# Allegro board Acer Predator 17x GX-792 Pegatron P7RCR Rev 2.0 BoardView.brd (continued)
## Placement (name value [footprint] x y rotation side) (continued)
C18107  10UF/6.3V  [VX_C0402_H28_SMALL]  114.38 63.02 0 bottom
C18108  1UF/6.3V  [VX_C0402_SMALL]  114.41 54.16 0 bottom
C18109  10UF/6.3V  [VX_C0402_H28_SMALL]  114.41 53.32 0 bottom
C18110  1UF/6.3V  [VX_C0402_SMALL]  114.41 52.48 0 bottom
C18111  10UF/6.3V  [VX_C0402_H28_SMALL]  114.38 63.89 0 bottom
C18112  1UF/6.3V  [VX_C0402_SMALL]  114.38 65.56 0 bottom
C75100  1UF/6.3V  [VX_C0402_SMALL]  155.29 91.11 180 top
C75101  1UF/6.3V  [VX_C0402_SMALL]  158.44 91.11 0 top
C75102  1UF/6.3V  [VX_C0402_SMALL]  160.02 91.1 0 top
C75103  1UF/6.3V  [VX_C0402_SMALL]  156.86 91.11 0 top
C75104  10uF/6.3V  [VX_C0603_H39_SMALL]  169.19 93.89 270 top
C75105  1UF/6.3V  [VX_C0402_SMALL]  155.29 89.72 180 top
C75106  1UF/6.3V  [VX_C0402_SMALL]  158.44 89.72 0 top
C75107  1UF/6.3V  [VX_C0402_SMALL]  160.01 89.72 0 top
C75108  1UF/6.3V  [VX_C0402_SMALL]  171.4 90.05 270 top
C75109  1UF/6.3V  [VX_C0402_SMALL]  163.21 98.1 180 top
C75110  1UF/6.3V  [VX_C0402_SMALL]  164.81 98.1 180 top
C75111  1UF/6.3V  [VX_C0402_SMALL]  163.21 96.7 180 top
C75112  1UF/6.3V  [VX_C0402_SMALL]  164.81 96.7 180 top
C75113  1UF/6.3V  [VX_C0402_SMALL]  166.38 96.7 0 top
C75114  1UF/6.3V  [VX_C0402_SMALL]  167.96 96.7 0 top
C75115  1UF/6.3V  [VX_C0402_SMALL]  167.96 100.89 0 top
C75116  10uF/6.3V  [VX_C0603_H39_SMALL]  161.57 93.93 270 top
C75117  10uF/6.3V  [VX_C0603_H39_SMALL]  164.48 90.41 90 top
C75118  10uF/6.3V  [VX_C0603_H39_SMALL]  166 90.36 90 top
C75119  10uF/6.3V  [VX_C0603_H39_SMALL]  157.23 97.37 270 top
C75120  1UF/6.3V  [VX_C0402_SMALL]  160.02 88.3 0 top
C75121  1UF/6.3V  [VX_C0402_SMALL]  164.74 88.27 180 top
C75122  330UF/2V  [VX_C7343D_H83]  157.82 97.79 180 top
C75123  330UF/2V  [VX_C7343D_H83]  165.41 89.9 0 top
C75124  10uF/6.3V  [VX_C0603_H39_SMALL]  159.92 93.95 90 top
C75125  10uF/6.3V  [VX_C0603_H39_SMALL]  154.01 93.88 90 top
C75126  330UF/2V  [VX_C7343D_H83]  202.8 145.24 180 top
C75127  47uF/4V  [VX_C0805_H57_SMALL]  201.83 141.61 0 top
C75128  1UF/6.3V  [VX_C0402_SMALL]  169.53 100.89 0 top
C75129  1UF/6.3V  [VX_C0402_SMALL]  158.81 102.95 180 top
C75130  1UF/6.3V  [VX_C0402_SMALL]  161.65 100.99 0 top
C75131  1UF/6.3V  [VX_C0402_SMALL]  153.71 86.9 180 top
C75132  1UF/6.3V  [VX_C0402_SMALL]  159.98 84.87 0 top
C75133  1UF/6.3V  [VX_C0402_SMALL]  163.28 86.8 180 top
C75134  1UF/6.3V  [VX_C0402_SMALL]  166.38 100.89 180 top
C75135  1UF/6.3V  [VX_C0402_SMALL]  157.22 102.95 0 top
C75136  1UF/6.3V  [VX_C0402_SMALL]  163.23 100.89 180 top
C75137  1UF/6.3V  [VX_C0402_SMALL]  169.91 102.92 0 top
C75138  1UF/6.3V  [VX_C0402_SMALL]  164.08 102.95 0 top
C75139  1UF/6.3V  [VX_C0402_SMALL]  160.04 86.9 0 top
C75140  1UF/6.3V  [VX_C0402_SMALL]  156.88 86.9 0 top
C75141  1UF/6.3V  [VX_C0402_SMALL]  166.44 86.8 180 top
C75142  1UF/6.3V  [VX_C0402_SMALL]  169.6 86.8 0 top
C75143  1UF/6.3V  [VX_C0402_SMALL]  169.76 84.85 0 top
C75144  0.1UF/6.3V  [VX_C0402_SMALL]  153.6 84.44 90 top
C75145  1UF/6.3V  [VX_C0402_SMALL]  152.25 72.75 0 top
C75146  4.7uF/16V  [VX_C0603_SMALL]  152.5 82.97 180 top
C75147  0.1UF/6.3V  [VX_C0402_SMALL]  154.83 84.04 180 top
C75148  0.1UF/6.3V  [VX_C0402_SMALL]  156.07 84.38 90 top
C75149  4.7uF/16V  [VX_C0603_SMALL]  149.42 71.74 180 top
C75150  1UF/6.3V  [VX_C0402_SMALL]  152.25 71.86 0 top
C75151  0.1UF/6.3V  [VX_C0402_SMALL]  157.46 82.28 270 top
C75152  1UF/6.3V  [VX_C0402_SMALL]  152.25 70.97 0 top
C75153  4.7uF/16V  [VX_C0603_SMALL]  149.43 70.5 180 top
C75154  0.1UF/6.3V  [VX_C0402_SMALL]  156.91 84.4 90 top
C75155  0.1UF/6.3V  [VX_C0402_SMALL]  155.3 82.02 270 top
C75156  4.7uF/16V  [VX_C0603_SMALL]  127.45 83.61 90 top
C75157  1UF/6.3V  [VX_C0402_SMALL]  123.95 83.4 180 top
C75158  0.1UF/6.3V  [VX_C0402_SMALL]  152.15 85.09 0 top
C75159  0.1UF/6.3V  [VX_C0402_SMALL]  152.15 84.27 0 top
C75160  330UF/2V  [VX_C7343D_H83]  140.76 148.9 0 top
C75161  330UF/2V  [VX_C7343D_H83]  141.76 148.42 0 bottom
C80002  22UF/6.3V  [VX_C0603_H39_SMALL]  105.55 118.4 180 top
C80004  22UF/6.3V  [VX_C0603_H39_SMALL]  88.92 129.83 180 top
C80005  10UF/25V  [VX_C0805_H57_SMALL]  59.29 172.96 180 top
C80006  10UF/25V  [VX_C0805_H57_SMALL]  59.29 171.18 180 top
C80008  22UF/6.3V  [VX_C0603_H39_SMALL]  93.49 116.24 180 top
C80009  22UF/6.3V  [VX_C0603_H39_SMALL]  70.21 138.03 270 bottom
C80010  22UF/6.3V  [VX_C0603_H39_SMALL]  68.94 138.03 270 bottom
C80012  22UF/6.3V  [VX_C0603_H39_SMALL]  82.28 137.27 270 bottom
C80013  22UF/6.3V  [VX_C0603_H39_SMALL]  77.07 137.27 270 bottom
C80017  22UF/6.3V  [VX_C0603_H39_SMALL]  83.2 116.1 0 top
C80019  1UF/16V  [VX_C0402_SMALL]  57.38 165.46 180 top
C80020  22UF/6.3V  [VX_C0603_H39_SMALL]  102 129.83 0 top
C80022  22UF/6.3V  [VX_C0603_H39_SMALL]  85.49 129.83 0 top
C80023  22UF/6.3V  [VX_C0603_H39_SMALL]  63.81 147.68 180 top
C80024  22UF/6.3V  [VX_C0603_H39_SMALL]  75.8 137.27 270 bottom
C80025  1UF/25V  [VX_C0402_H24_SMALL]  67.67 169.91 90 top
C80026  22UF/6.3V  [VX_C0603_H39_SMALL]  102.76 118.4 0 top
C80027  1000PF/50V  [VX_C0402_SMALL]  53.57 171.81 180 top
C80029  22UF/6.3V  [VX_C0603_H39_SMALL]  100.69 146.16 0 top
C80031  22UF/6.3V  [VX_C0603_H39_SMALL]  110.98 129.67 90 top
C80032  22UF/6.3V  [VX_C0603_H39_SMALL]  63.81 148.95 180 top
C80036  22UF/6.3V  [VX_C0603_H39_SMALL]  98.34 129.83 180 top
C80038  22UF/6.3V  [VX_C0603_H39_SMALL]  102.76 117.13 0 top
C80039  22UF/6.3V  [VX_C0603_H39_SMALL]  63.81 146.41 180 top
C80040  22UF/6.3V  [VX_C0603_H39_SMALL]  93.11 129.93 180 top
C80041  1500PF/50V  [VX_C0603_SMALL]  90 159.11 0 top
C80042  0.22UF/16V  [VX_C0402_SMALL]  64.12 174.23 270 top
C80044  22UF/6.3V  [VX_C0603_H39_SMALL]  107.97 124.36 0 top
C80046  1500PF/50V  [VX_C0603_SMALL]  48.88 172.7 270 top
C80049  22UF/6.3V  [VX_C0603_H39_SMALL]  118.8 126.5 180 top
C80050  22UF/6.3V  [VX_C0603_H39_SMALL]  84.44 146.54 0 top
C80052  0.22UF/16V  [VX_C0402_SMALL]  57.26 168.05 270 top
C80055  22UF/6.3V  [VX_C0603_H39_SMALL]  104.54 129.83 0 top
C80056  1500PF/50V  [VX_C0603_SMALL]  59.54 164.95 0 top
C80057  22UF/6.3V  [VX_C0603_H39_SMALL]  81.81 129.83 180 top
C80059  22UF/6.3V  [VX_C0603_H39_SMALL]  100.69 144.89 0 top
C80062  22UF/6.3V  [VX_C0603_H39_SMALL]  84.82 137.27 270 bottom
C80064  1UF/16V  [VX_C0402_SMALL]  65 174.73 270 top
C80066  1UF/25V  [VX_C0402_H24_SMALL]  100.76 160 0 top
C80068  22UF/6.3V  [VX_C0603_H39_SMALL]  63.81 150.22 180 top
C80069  22UF/6.3V  [VX_C0603_H39_SMALL]  86.53 116.16 180 top
C80070  10UF/25V  [VX_C0805_H57_SMALL]  53.57 174.99 180 top
C80073  22UF/6.3V  [VX_C0603_H39_SMALL]  101.78 137.47 270 top
C80074  1000PF/50V  [VX_C0402_SMALL]  60.31 169.4 270 top
C80075  22UF/6.3V  [VX_C0603_H39_SMALL]  97.88 117.08 0 top
C80076  10UF/25V  [VX_C0805_H57_SMALL]  53.57 173.21 180 top
C80077  22UF/6.3V  [VX_C0603_H39_SMALL]  86.09 137.27 270 bottom
C80078  22UF/6.3V  [VX_C0603_H39_SMALL]  103.36 137.47 270 top
C80079  10UF/25V  [VX_C0805_H57_SMALL]  53.57 176.77 180 top
C80082  1UF/25V  [VX_C0402_H24_SMALL]  53.7 164.45 0 top
C80083  22UF/6.3V  [VX_C0603_H39_SMALL]  100.5 118.4 180 top
C80087  22UF/6.3V  [VX_C0603_H39_SMALL]  84.44 145.27 0 top
C80091  10UF/25V  [VX_C0805_H57_SMALL]  59.29 174.73 180 top
C80092  22UF/6.3V  [VX_C0603_H39_SMALL]  90.66 144.63 180 top
C80095  22UF/6.3V  [VX_C0603_H39_SMALL]  88.77 116.16 0 top
C80098  22UF/6.3V  [VX_C0603_H39_SMALL]  83.55 137.27 270 bottom
C80102  22UF/6.3V  [VX_C0603_H39_SMALL]  71.48 138.03 270 bottom
C80103  0.068UF/16V  [VX_C0402_SMALL]  49 190.18 90 top
C80104  0.1UF/25V  [VX_C0402_SMALL]  48.11 188.83 0 bottom
C80105  6800PF/25V  [VX_C0402_SMALL]  49.38 188.37 270 bottom
C80106  2200PF/50V  [VX_C0402_SMALL]  50.15 185.27 180 bottom
C80107  0.22UF/25V  [VX_C0603_SMALL]  54.72 188.75 180 top
C80108  1UF/25V  [VX_C0402_H24_SMALL]  54.66 188.27 180 bottom
C80109  0.1UF/25V  [VX_C0402_SMALL]  50.15 179.61 0 bottom
C80110  0.1UF/25V  [VX_C0402_SMALL]  69.3 180.75 0 bottom
C80111  0.1UF/25V  [VX_C0402_SMALL]  49.89 190.18 90 top
C80112  22UF/6.3V  [VX_C0603_H39_SMALL]  71.1 129.9 90 top
C80113  22UF/6.3V  [VX_C0603_H39_SMALL]  73.26 137.27 270 bottom
C80114  22UF/6.3V  [VX_C0603_H39_SMALL]  74.53 137.27 270 bottom
C80115  22UF/6.3V  [VX_C0603_H39_SMALL]  53.6 150.3 0 top
C80116  22UF/6.3V  [VX_C0603_H39_SMALL]  78.34 137.27 270 bottom
C80117  22UF/6.3V  [VX_C0603_H39_SMALL]  67.67 138.03 270 bottom
C80118  22UF/6.3V  [VX_C0603_H39_SMALL]  66.4 138.03 270 bottom
C80119  22UF/6.3V  [VX_C0603_H39_SMALL]  81.01 137.27 270 bottom
C80121  22UF/6.3V  [VX_C0603_H39_SMALL]  79.61 137.27 270 bottom
C80122  10PF/50V  [VX_C0402_SMALL]  107.82 115.73 180 top
C80123  2.2NF/50V  [VX_C0402_SMALL]  107.79 116.64 180 top
C80124  10PF/50V  [VX_C0402_SMALL]  74.44 129.44 270 top
C80125  2.2NF/50V  [VX_C0402_SMALL]  75.33 129.44 270 top
C80126  10PF/50V  [VX_C0402_SMALL]  107.68 125.71 180 top
C80127  2.2NF/50V  [VX_C0402_SMALL]  107.68 132.32 180 top
C80128  22UF/6.3V  [VX_C0603_H39_SMALL]  100.69 143.62 0 top
C80129  22UF/6.3V  [VX_C0603_H39_SMALL]  103.66 153.73 270 top
C80130  22UF/6.3V  [VX_C0603_H39_SMALL]  118.8 127.77 180 top
C80131  22UF/6.3V  [VX_C0603_H39_SMALL]  102.39 153.73 270 top
C80132  22UF/6.3V  [VX_C0603_H39_SMALL]  118.8 129.17 180 top
C80133  0.1UF/25V  [VX_C0402_SMALL]  50.15 178.72 0 bottom
C80134  0.1UF/25V  [VX_C0402_SMALL]  70.16 126.25 0 bottom
CE1225  100UF/6.3V  [VX_C3528]  307.47 27.29 0 bottom
CE1801  330UF/2V  [VX_C7343D_H83]  56.62 104.76 90 top
CE1802  330UF/2V  [VX_C7343D_H83]  44.68 109.96 270 bottom
CE1803  330UF/2V  [VX_C7343D_H83]  54.84 109.96 270 bottom
CE1804  330UF/2V  [VX_C7343D_H83]  49.76 109.96 270 bottom
CE5502  100UF/6.3V  [VX_C3528]  308.24 59.16 90 top
CE5503  100UF/6.3V  [VX_C3528]  307.93 70.21 90 top
CE6703  100UF/6.3V  [VX_C3528]  32.11 95.61 180 bottom
CE8000  470UF/2V  [VX_C7343D_3P]  92.82 148.83 180 bottom
CE8001  470UF/2V  [VX_C7343D_3P]  82.53 148.83 0 bottom
CE8004  470UF/2V  [VX_C7343D_3P]  52.43 153.78 0 top
CE8007  470UF/2V  [VX_C7343D_3P]  62.97 153.78 180 top
CE8017  15UF/25V  [VX_C3528_SANYO_H79]  70.72 153.78 180 bottom
CE8018  15UF/25V  [VX_C3528_SANYO_H79]  70.72 157.21 180 bottom
CE8020  15UF/25V  [VX_C3528_SANYO_H79]  70.72 160.64 180 bottom
CE8021  15UF/25V  [VX_C3528_SANYO_H79]  85.08 178.95 90 bottom
CE8022  15UF/25V  [VX_C3528_SANYO_H79]  88.51 178.95 90 bottom
CE8023  15UF/25V  [VX_C3528_SANYO_H79]  86.62 179.18 90 top
CE8024  15UF/25V  [VX_C3528_SANYO_H79]  70.34 172.32 180 bottom
CE8025  15UF/25V  [VX_C3528_SANYO_H79]  70.34 175.75 180 bottom
CE8026  15UF/25V  [VX_C3528_SANYO_H79]  70.34 175.75 180 top
CE8100  220UF/6.3V  [VX_CESMD_260X260_H240_COLAY]  281.92 80.12 270 bottom
CE8101  220UF/6.3V  [VX_CESMD_260X260_H240_COLAY]  255.89 30.46 180 bottom
CE8301  470UF/2V  [VX_C7343D_3P]  26.27 87.36 0 top
CE8700  470UF/2V  [VX_C7343D_3P]  140.7 154.62 0 bottom
CE8701  470UF/2V  [VX_C7343D_3P]  158.22 154.79 180 bottom
CE8702  470UF/2V  [VX_C7343D_3P]  158.09 148.95 180 top
CE8703  470UF/2V  [VX_C7343D_3P]  158.1 154.79 180 top
CE8704  470UF/2V  [VX_C7343D_3P]  182.35 154.79 180 bottom
CE8705  470UF/2V  [VX_C7343D_3P]  187.26 156.06 180 top
CE8706  470UF/2V  [VX_C7343D_3P]  158.1 148.95 180 bottom
CE8707  470UF/2V  [VX_C7343D_3P]  167.75 154.79 0 bottom
CE8708  470UF/2V  [VX_C7343D_3P]  167.87 154.79 0 top
CE8709  470UF/2V  [VX_C7343D_3P]  167.86 148.95 0 top
CE8710  470UF/2V  [VX_C7343D_3P]  167.75 148.95 0 bottom
CE8711  470UF/2V  [VX_C7343D_3P]  140.7 154.72 0 top
CE8716  100UF/25V  [VX_CESMD_260X260_PANASONIC]  166.99 188.42 270 bottom
CE8717  100UF/25V  [VX_CESMD_260X260_PANASONIC]  144.76 188.32 270 bottom
CE8718  100UF/25V  [VX_CESMD_260X260_PANASONIC]  156.01 188.32 270 bottom
CE8719  100UF/25V  [VX_CESMD_260X260_PANASONIC]  178.29 188.42 270 bottom
CE8900  470UF/2V  [VX_C7343D_H83]  222.08 79.74 180 bottom
CE8901  470UF/2V  [VX_C7343D_H83]  213.79 93.07 270 bottom
CE8902  470UF/2V  [VX_C7343D_H83]  222.36 79.74 180 top
CE8903  470UF/2V  [VX_C7343D_H83]  213.98 92.82 270 top
CE9701  470UF/2V  [VX_C7343D_3P]  189.85 149.05 0 top
CE9702  470UF/2V  [VX_C7343D_3P]  202.57 149.89 180 bottom
CE9703  470UF/2V  [VX_C7343D_3P]  189.85 149.08 0 bottom
CE9704  470UF/2V  [VX_C7343D_3P]  202.62 150.63 180 top
CN1  33PF/50V  [VX_C_ARRAY_8P_79X49_H39]  117.14 17.35 0 top
CN2  33PF/50V  [VX_C_ARRAY_8P_79X49_H39]  119.93 17.35 0 top
CN3  33PF/50V  [VX_C_ARRAY_8P_79X49_H39]  123.11 17.35 0 top
CN4  33PF/50V  [VX_C_ARRAY_8P_79X49_H39]  126.23 17.35 0 top
CN5  33PF/50V  [VX_C_ARRAY_8P_79X49_H39]  131.95 17.35 0 top
CN6  33PF/50V  [VX_C_ARRAY_8P_79X49_H39]  135.12 17.35 0 top
CN7  33PF/50V  [VX_C_ARRAY_8P_79X49_H39]  129.03 17.35 0 top
CON1  FPC_CON_8P  [VX_FPC_8P_20_2H_RA_ACE_B]  236.7 188.1 0 top
CON1201  USB_CON_24P  [VX_USB_24P_10HD_RA_ACON]  318.85 33.05 90 top
CON1600  DDR4_SO_260P  [VX_DDR4_260P_20_4HD_FOX]  76 60.7 0 top
CON1601  DDR4_SO_260P  [VX_DDR4_260P_20_4HOD_REV_FO]  74 60.7 180 bottom
CON1700  DDR4_SO_260P  [VX_DDR4_260P_20_4H_RE_H177]  76 48.7 180 top
CON1701  DDR4_SO_260P  [VX_DDR4_260P_20_4H_REV_ARGO]  74 48.7 180 bottom
CON2800  BATT_HOLDER_2P  [VX_BATHOLDER_2P_2HOLD]  298 61.9 270 bottom
CON3100  FPC_CON_26P  [VX_FPC_26P_39_2H_RA_B]  118 7.7 180 bottom
CON3104  FPC_CON_14P  [VX_FPC_14P_20_2H_ACE_B]  209 18.7 180 bottom
CON3110  FPC_CON_14P  [VX_FPC_14P_20_2HD_RA_ENTERY]  189.75 16.8 180 bottom
CON3400  LAN_JACK_8P  [VX_LAN_JACK_8P_2HD_SAN_LF2]  317.7 145.9 270 bottom
CON3600  WTOB_CON_4P  [VX_WTOB_4P_39_2H_ACES]  7 22.9 90 bottom
CON3700  WtoB_CON_4P  [VX_WTOB_4P_49_2HOLD_RA]  232 18.7 180 bottom
CON4400  FPC_CON_12P  [VX_FPC_12P_20_2HD_B]  144 5.7 180 bottom
CON4402  FPC_CON_12P  [VX_FPC_12P_20_2HD_B]  175.75 17.4 180 bottom
CON4500  WTOB_CON_40P  [VX_WTOB_40P_20_6HD_STAR]  112.5 186.2 0 top
CON4601  DISPLAY_CON_20P  [VX_DISPLAY_20P_39_4H_ACON]  320.02 123.95 90 top
CON4800  HDMI_CON_19P  [VX_HDMI_19P_4HLD_ACON]  321 100.85 90 top
CON5000  WTOB_CON_4P  [VX_WTOB_4P_49_2HD_ACE]  52 118.7 180 bottom
CON5001  WTOB_CON_4P  [VX_WTOB_4P_49_2HD_ACE]  261.8 88.15 0 bottom
CON5002  WTOB_CON_3P  [VX_WTOB_3P_49_2H_RA_ACE]  82.67 6.45 270 bottom
CON5100  WTOB_CON_20P  [VX_WTOB_20P_20_6HOLD_ENTERY]  20 11.9 180 bottom
CON5102  NGFF_67P  [VX_NGFF_67P_20_4HOLD_H165]  36.3 29.7 270 bottom
CON5103  MINI_PCI_67P  [VX_MINI_PCI_67P_20_4HLD_LOT]  25 29.7 270 bottom
CON5104  MINI_PCI_67P  [VX_MINI_PCI_67P_20_4HLD_LOT]  43.5 9.4 180 bottom
CON5300  MINI_PCI_67P  [VX_MINI_PCI_67P_20_4H_H128]  297 96.9 0 bottom
CON5500  USB_CON_9P  [VX_USB_9P_4HOLD_RA_SINGA]  312.9 52.2 90 top
CON5501  USB_CON_9P  [VX_USB_9P_4HOLD_RA_SINGA]  312.9 79.6 90 top
CON5602  FPC_CON_28P  [VX_FPC_CON_28P_20_2H_AC_B]  88.5 187.1 0 bottom
CON6000  WTOB_CON_10P  [VX_WTOB_10P_79_2HD_RA_CUIL]  295 18.42 180 bottom
CON6001  WTOB_CON_10P  [VX_WTOB_10P_59_4HOLD_RA_TYU]  11.5 69.4 90 bottom
CON6002  TACT_SWITCH_4P  [VX_SW_4P_146_S205_2HOLD_H63]  297 83.7 0 bottom
CON6003  SWITCH_4P  [VX_SW_4P_185X185]  26.99 71.9 90 bottom
CON6004  WTOB_CON_2P  [VX_WTOB_2P_49_2HOLD_ACE]  12.5 82.3 0 bottom
CON6700  FPC_CON_45P  [VX_FPC_45P_20_2H_RA_ENTE_B]  11 45.7 90 bottom
CON6701  WTOB_CON_5P  [VX_WTOB_5P_39_2HOLD_ENTE]  21.49 82.99 180 bottom
D1201  ESD8011MUT5G  [VX_ESD_2P_24X13_PAD8X10]  314.05 31.67 90 top
D1202  ESD8011MUT5G  [VX_ESD_2P_24X13_PAD8X10]  314.05 30.44 270 top
D1203  ESD8011MUT5G  [VX_ESD_2P_24X13_PAD8X10]  316.19 30.33 270 bottom
D1204  ESD8011MUT5G  [VX_ESD_2P_24X13_PAD8X10]  316.19 31.6 90 bottom
D1205  ESD8011MUT5G  [VX_ESD_2P_24X13_PAD8X10]  316.19 34.4 270 bottom
D1206  ESD8011MUT5G  [VX_ESD_2P_24X13_PAD8X10]  316.19 35.67 90 bottom
D1207  ESD8011MUT5G  [VX_ESD_2P_24X13_PAD8X10]  314.05 35.66 90 top
D1208  ESD8011MUT5G  [VX_ESD_2P_24X13_PAD8X10]  314.05 34.42 270 top
D1209  AZ5725-01F  [VX_ESD_2P_33_39X24_COLAY]  309.73 28.05 90 top
D1301  RB751V-40  [VX_SOD323_H35]  280.45 88.88 180 top
D2301  CH751H-40AGP  [VX_SOD323_H39]  242.22 79.53 180 top
D2401  CH751H-40AGP  [VX_SOD323_H39]  254.49 68.33 270 top
D2402  CH751H-40AGP  [VX_SOD323_H39]  252.58 70.59 270 top
D2801  0.8V/0.2mA  [VX_SOT323]  276.5 66.01 0 bottom
D3101  AZ5725-01F  [VX_ESD_2P_33_39X24_COLAY]  209.4 23.6 0 top
D3102  AZ5725-01F  [VX_ESD_2P_33_39X24_COLAY]  207.24 23.6 180 top
D3400  AZ5725-01F  [VX_ESD_2P_33_39X24_COLAY]  308.84 138.41 45 top
D3600  AZ5725-01F  [VX_ESD_2P_34_39X24_INPAQ]  4.81 45.96 270 top
D3601  CH751H-40AGP  [VX_SOD323_H39]  16.31 20.91 0 top
D4502  1V/0.1A  [VX_SOT323]  95.28 189.85 270 top
D4503  CH751H-40AGP  [VX_SOD323_H39]  91.29 189.47 90 top
D4800  BAW56W  [VX_SOT323]  308.34 88.43 180 top
D5000  0.8V/0.2mA  [VX_SOT323]  59.16 113.22 180 bottom
D5001  BAW56W  [VX_SOT323]  59.16 109.63 180 bottom
D5002  0.8V/0.2mA  [VX_SOT323]  266.15 87.08 180 top
D5003  BAW56W  [VX_SOT323]  261.88 86.28 90 top
D5004  1V/0.1A  [VX_SOT323]  136.89 39.5 180 top
D5301  CH751H-40AGP  [VX_SOD323_H39]  283.06 94.47 90 bottom
D5302  CH751H-40AGP  [VX_SOD323_H39]  281.16 94.47 90 bottom
D5303  1SS355AGP  [VX_SOD323_H37]  299.57 93.91 270 top
D5308  1SS355AGP  [VX_SOD323_H37]  299.57 98.53 270 top
D5501  AZ5725-01F  [VX_ESD_2P_33_39X24_COLAY]  307.45 47.57 270 bottom
D5502  AZ5725-01F  [VX_ESD_2P_33_39X24_COLAY]  308.76 47.57 270 bottom
D5503  AZ5725-01F  [VX_ESD_2P_33_39X24_COLAY]  307.88 78.44 270 bottom
D5504  AZ5725-01F  [VX_ESD_2P_33_39X24_COLAY]  307.88 80.6 90 bottom
D5505  AZ5725-01F  [VX_ESD_2P_33_39X24_COLAY]  308.34 63.86 90 top
D5506  AZ5725-01F  [VX_ESD_2P_33_39X24_COLAY]  309.2 74.91 90 top
D5601  1V/0.1A  [VX_SOT323]  94.85 185.3 0 top
D6002  AZ5725-01F  [VX_ESD_2P_33_39X24_COLAY]  293.1 28.94 270 bottom
D6003  AZ5725-01F  [VX_ESD_2P_33_39X24_COLAY]  291.6 30.36 90 bottom
D6005  1.25V/0.15A  [VX_SOT23_H49]  287.13 28.81 180 bottom
D6006  1.25V/0.15A  [VX_SOT23_H49]  287.13 32.11 180 bottom
D6701  AZ5725-01F  [VX_ESD_2P_33_39X24_COLAY]  16.75 32 270 bottom
D6702  AZ5725-01F  [VX_ESD_2P_33_39X24_COLAY]  16.75 34.2 90 bottom
D6703  AZ5725-01F  [VX_ESD_2P_33_39X24_COLAY]  12.63 38.97 0 top
D7401  0.8V/0.2mA  [VX_SOT323]  146.54 47.48 180 bottom
D7402  0.8V/0.2mA  [VX_SOT323]  151.11 59.09 90 bottom
D7403  0.8V/0.2mA  [VX_SOT323]  144.84 59.09 0 top
D7404  1.2V/0.1A  [VX_SOD323_H37]  141.71 58.91 180 bottom
D7405  0.8V/0.2mA  [VX_SOT323]  141.33 52.81 0 bottom
D7406  0.8V/0.2mA  [VX_SOT323]  141.59 62.47 180 top
D7407  1.2V/0.1A  [VX_SOD323_H37]  123.93 150.22 270 bottom
D8102  1V/0.2A  [VX_SOT23_H43]  259.7 73.31 90 top
D8103  1V/0.2A  [VX_SOT23_H43]  255.12 73.03 90 top
D8200  1.2V/0.1A  [VX_SOD323_H37]  191.37 18.65 0 top
D8300  1.2V/0.1A  [VX_SOD323_H37]  27.61 42.88 180 top
D8301  1.2V/0.1A  [VX_SOD323_H37]  32.44 42.88 180 top
D8601  1.2V/0.1A  [VX_SOD323_H37]  123.35 54.29 180 bottom
D8701  1.2V/0.1A  [VX_SOD323_H37]  124.44 160.13 0 bottom
D8800  0.8V/0.2mA  [VX_SOT323]  283.9 31.03 270 top
D8801  0.8V/0.2mA  [VX_SOT323]  3.94 61.63 180 top
D8804  1.2V/0.1A  [VX_SOD323_H37]  218.09 23.88 0 top
D8805  SBR2U30P1-7  [VX_POWERDI123]  266.33 34.88 0 top
D8900  1.2V/0.1A  [VX_SOD323_H37]  251.31 80.4 180 bottom
D9200  CH751H-40AGP  [VX_SOD323_H39]  178.57 42.25 180 top
D9201  1.2V/0.1A  [VX_SOD323_H37]  181.08 36.43 180 top
D9202  CH751H-40AGP  [VX_SOD323_H39]  185.91 36.23 270 top
D9400  1.2V/0.1A  [VX_SOD323_H37]  101.45 160.64 90 bottom
D9500  1.2V/0.1A  [VX_SOD323_H37]  101.2 14.84 180 bottom
D9600  1.2V/0.1A  [VX_SOD323_H37]  115.17 141.08 90 bottom
D9700  1.2V/0.1A  [VX_SOD323_H37]  208.01 186.54 90 top
H11  C138D118  [NB_H_RTD118_P2_S]  317.2 65.9 0 top
H21  RT335X350CBD118  [NB_H_RT335X350CBD118_P2_S]  319.8 21.6 0 top
H31  CT276B315D118  [VX_H_CT276CB315D118_P2]  43.5 166.8 180 top
H32  RT335X315B315D118  [NB_H_RT335X315B315D118_P2_S]  73.9 189.7 180 top
H33  ST335CB315D118  [VX_H_ST335CB315D118_P2]  316.5 163.9 180 bottom
H34  ST335CB315D118  [VX_H_ST335CB315D118_P2]  307.5 163.9 90 bottom
H35  RT335X315B315D118  [NB_H_RT335X315B315D118_P2_S]  188 189.7 0 top
H36  ST335CB315D118  [VX_H_ST335CB315D118_P2]  135.5 188.7 90 top
H51  CT276B315D118  [VX_H_CT276CB315D118_P2]  7 11.9 180 top
H52  CT276B315D118  [VX_H_CT276CB315D118_P2]  250 20.9 0 top
H53  CT276B315D118  [VX_H_CT276CB315D118_P2]  119.5 86.9 0 top
H54  CT276B315D118  [VX_H_CT276CB315D118_P2]  140 20.9 0 top
H55  CT276B315D118  [VX_H_CT276CB315D118_P2]  272 90.9 0 top
H56  CT276B315D118  [VX_H_CT276CB315D118_P2]  201 27.9 0 top
H60  CT256B256D130  [NB_NUT_CT256B256D130_LF2]  130.6 138.9 180 bottom
H61  CT256BD146  [NB_NUT_CT256B256D146_LF2]  106.62 145.85 180 bottom
H62  CT256BD146  [NB_NUT_CTB256D146_H91_LF2]  297 125.25 180 bottom
H63  CT256B256D130  [NB_NUT_CT256B256D130_LF2]  130.6 48.9 180 bottom
H64  CT256BD146  [NB_NUT_CT256B256D146_LF2]  68.14 113.56 180 bottom
H65  CT256BD146  [NB_NUT_C256D146_H134_LF2]  114.55 29.7 180 bottom
H66  CT256BD146  [NB_NUT_CT256B256D146_LF2]  115.34 96.38 180 bottom
H68  CT256B256D130  [NB_NUT_CT256B256D130_LF2]  192.6 138.9 270 bottom
H69  CT256B256D130  [NB_NUT_CT256B256D130_LF2]  192.6 48.9 180 bottom
H70  CT276B315D118  [VX_H_CT276CB315D118_P2]  50 97.9 0 top
H71  CT276B315D118  [VX_H_CT276CB315D118_P2]  27 60.9 0 top
H800  C102D102N  [HOLE_C102D102N]  249.05 189.45 0 bottom
H803  O134X102DO134X102N  [HOLE_O134X102DO134X102N]  223.95 189.45 0 bottom
H804  ST335CB315D118  [VX_H_ST335CB315D118_P2]  255.75 189.45 0 bottom
H805  ST335CB315D118  [VX_H_ST335CB315D118_P2]  218.25 189.45 0 bottom
H6901  O122X102DO122X102N  [HOLE_O122X102DO122X102N]  128.5 188.7 270 top
H6902  C102D102N  [HOLE_C102D102N]  75.8 10.5 270 top
H6903  O122X102DO122X102N  [HOLE_O122X102DO122X102N]  299.5 163.9 180 bottom
IC220  1UF/6.3V  [VX_C0402_SMALL]  1.96 55.53 0 top
IC221  1UF/6.3V  [VX_C0402_SMALL]  2.52 51.62 90 top
IU202  APL3518ABI-TRG  [VX_SOT23_S5_H57]  5.14 55.84 0 top
IU203  APL3518ABI-TRG  [VX_SOT23_S5_H57]  6.25 52.13 0 top
JP1001  3MM_OPEN_5MIL  [3MM_OPEN_5MIL_M1M2]  72.62 97.01 90 top
JP1201  3MM_OPEN_5MIL  [3MM_OPEN_5MIL_M1M2]  282.94 61.68 0 top
JP1601  3MM_OPEN_5MIL  [3MM_OPEN_5MIL_M1M2]  48.49 104.63 90 top
JP1701  3MM_OPEN_5MIL  [3MM_OPEN_5MIL_M1M2]  48.49 109.84 90 top
JP2601  2MM_OPEN_5MIL  [2MM_OPEN_5MIL_M1M2]  212.96 59.29 180 top
JP2602  1MM_OPEN_M1M2  [1MM_OPEN_5MIL_M1M2]  217.53 59.04 0 top
JP5601  SGL_JUMP  [NB_OPEN2_5MIL_PT]  84.94 189.59 90 top
JP8050  SHORT_PIN  [NB_PWR_FB_SHORT_PT]  79.13 155.56 180 bottom
JP8051  SHORT_PIN  [NB_PWR_FB_SHORT_PT]  82.63 155.56 0 bottom
JP8052  SHORT_PIN  [NB_PWR_FB_SHORT_PT]  79.13 171 180 bottom
JP8053  SHORT_PIN  [NB_PWR_FB_SHORT_PT]  82.63 170.97 0 bottom
JP8054  SHORT_PIN  [NB_PWR_FB_SHORT_PT]  79.13 163.3 180 bottom
JP8055  SHORT_PIN  [NB_PWR_FB_SHORT_PT]  82.63 163.3 0 bottom
JP8056  SHORT_PIN  [NB_PWR_FB_SHORT_PT]  92.94 150.48 180 top
JP8057  SHORT_PIN  [NB_PWR_FB_SHORT_PT]  54.31 160.38 0 top
JP8058  SHORT_PIN  [NB_PWR_FB_SHORT_PT]  50.81 160.38 180 top
JP8059  SHORT_PIN  [NB_PWR_FB_SHORT_PT]  64.47 160.38 0 top
JP8060  SHORT_PIN  [NB_PWR_FB_SHORT_PT]  60.97 160.38 180 top
JP8061  SHORT_PIN  [NB_PWR_FB_SHORT_PT]  96.27 150.48 0 top
JP8100  1MM_OPEN_M1M2  [1MM_OPEN_5MIL_M1M2]  266.68 60.31 270 top
JP8101  3MM_OPEN_5MIL  [3MM_OPEN_5MIL_M1M2]  283.44 74.47 0 top
JP8102  3MM_OPEN_5MIL  [3MM_OPEN_5MIL_M1M2]  247.25 30.53 0 top
JP8103  SHORT_PIN  [NB_PWR_FB_SHORT_PT]  281.41 79.48 90 bottom
JP8104  SHORT_PIN  [NB_PWR_FB_SHORT_PT]  282.3 79.48 90 bottom
JP8105  SHORT_PIN  [NB_PWR_FB_SHORT_PT]  255.25 30.46 180 bottom
JP8106  1MM_OPEN_M1M2  [1MM_OPEN_5MIL_M1M2]  255.76 55.86 90 top
JP8107  1MM_OPEN_M1M2  [1MM_OPEN_5MIL_M1M2]  255.25 76.94 90 bottom
JP8108  3MM_OPEN_5MIL  [3MM_OPEN_5MIL_M1M2]  248.24 30.96 180 bottom
JP8109  3MM_OPEN_5MIL  [3MM_OPEN_5MIL_M1M2]  243.03 28.75 180 bottom
JP8110  3MM_OPEN_5MIL  [3MM_OPEN_5MIL_M1M2]  278.24 74.47 0 top
JP8111  3MM_OPEN_5MIL  [3MM_OPEN_5MIL_M1M2]  273.03 74.47 0 top
JP8112  2MM_OPEN_5MIL  [2MM_OPEN_5MIL_M1M2]  252.71 29.83 180 top
JP8200  SHORT_PIN  [NB_PWR_FB_SHORT_PT]  202.16 11.92 90 top
JP8202  3MM_OPEN_5MIL  [3MM_OPEN_5MIL_M1M2]  209.53 53.58 0 top
JP8300  SHORT_PIN  [NB_PWR_FB_SHORT_PT]  24.24 52.18 270 top
JP8301  1MM_OPEN_M1M2  [1MM_OPEN_5MIL_M1M2]  23.35 55.48 180 top
JP8302  3MM_OPEN_5MIL  [3MM_OPEN_5MIL_M1M2]  42.08 107.93 90 top
JP8303  SHORT_PIN  [NB_PWR_FB_SHORT_PT]  35.64 102.62 180 top
JP8304  SHORT_PIN  [NB_PWR_FB_SHORT_PT]  36.02 103.41 90 top
JP8305  3MM_OPEN_5MIL  [3MM_OPEN_5MIL_M1M2]  42.08 97.01 90 top
JP8306  3MM_OPEN_5MIL  [3MM_OPEN_5MIL_M1M2]  42.08 102.6 90 top
JP8307  1MM_OPEN_M1M2  [1MM_OPEN_5MIL_M1M2]  41.51 112.12 270 top
JP8400  1MM_OPEN_M1M2  [1MM_OPEN_5MIL_M1M2]  216.13 30.33 0 top
JP8601  SHORT_PIN  [NB_PWR_FB_SHORT_PT]  127.43 72.55 180 top
JP8602  3MM_OPEN_5MIL  [3MM_OPEN_5MIL_M1M2]  125.96 79.23 180 top
JP8603  SHORT_PIN  [NB_PWR_FB_SHORT_PT]  127.44 71.08 180 top
JP8701  SHORT_PIN  [NB_PWR_FB_SHORT_PT]  179.43 167.39 270 bottom
JP8702  SHORT_PIN  [NB_PWR_FB_SHORT_PT]  179.43 162.29 90 bottom
JP8703  SHORT_PIN  [NB_PWR_FB_SHORT_PT]  140.19 167.37 270 bottom
JP8704  SHORT_PIN  [NB_PWR_FB_SHORT_PT]  140.19 162.29 90 bottom
JP8705  SHORT_PIN  [NB_PWR_FB_SHORT_PT]  154.69 167.37 270 bottom
JP8706  SHORT_PIN  [NB_PWR_FB_SHORT_PT]  154.69 162.29 90 bottom
JP8707  SHORT_PIN  [NB_PWR_FB_SHORT_PT]  167.62 167.37 270 bottom
JP8708  SHORT_PIN  [NB_PWR_FB_SHORT_PT]  167.62 162.29 90 bottom
JP8800  3MM_OPEN_5MIL  [3MM_OPEN_5MIL_M1M2]  307.77 18.02 90 top
JP8801  SHORT_PIN  [NB_PWR_FB_SHORT_PT]  22.33 82.24 270 top
JP8802  SHORT_PIN  [NB_PWR_FB_SHORT_PT]  22.33 80.97 90 top
JP8803  3MM_OPEN_5MIL  [3MM_OPEN_5MIL_M1M2]  307.77 23.22 90 top
JP8804  SHORT_PIN  [NB_PWR_FB_SHORT_PT]  298.68 23.98 0 top
JP8805  SHORT_PIN  [NB_PWR_FB_SHORT_PT]  300.46 23.98 180 top
JP9000  SHORT_PIN  [NB_PWR_FB_SHORT_PT]  168.13 31.6 0 top
JP9300  SGL_JUMP  [NB_OPEN2_5MIL_PT]  59.45 188.56 0 top
JP9301  SGL_JUMP  [NB_OPEN2_5MIL_PT]  256.9 79.86 0 top
JP9302  SGL_JUMP  [NB_OPEN2_5MIL_PT]  255.07 77.68 180 top
JP9303  SGL_JUMP  [NB_OPEN2_5MIL_PT]  256.77 67.29 270 top
JP9400  3MM_OPEN_5MIL  [3MM_OPEN_5MIL_M1M2]  110.34 157.78 0 bottom
JP9401  SHORT_PIN  [NB_PWR_FB_SHORT_PT]  106.8 160.51 0 bottom
JP9402  1MM_OPEN_M1M2  [1MM_OPEN_5MIL_M1M2]  114.53 157.94 0 bottom
JP9500  3MM_OPEN_5MIL  [3MM_OPEN_5MIL_M1M2]  112.06 11.16 270 top
JP9501  SHORT_PIN  [NB_PWR_FB_SHORT_PT]  107.8 12.05 270 top
JP9502  SHORT_PIN  [NB_PWR_FB_SHORT_PT]  107.8 8.36 90 top
JP9600  2MM_OPEN_5MIL  [2MM_OPEN_5MIL_M1M2]  123.68 130.03 0 bottom
JP9601  SHORT_PIN  [NB_PWR_FB_SHORT_PT]  117.2 135.49 0 bottom
JP9602  SHORT_PIN  [NB_PWR_FB_SHORT_PT]  117.2 134.09 0 bottom
JRST5001  0Ohm  [VX_R0603_0OHM_H28_SMALL]  132.06 31.22 90 top
L1101  0.6uH  [VX_INDUCTOR_2P_157X157_COIL]  300.16 49.38 90 top
L1106  1UH  [VX_L0603_H37_SMALL]  279.38 44.05 90 bottom
L1201  80ohm  [VX_CHOKE_4P_49X39_MUR]  307.02 42.27 270 bottom
L1202  80ohm  [VX_CHOKE_4P_49X39_MUR]  304.45 38.08 270 bottom
L2601  180Ohm/100Mhz  [VX_L0603_H37_SMALL]  246.74 73.51 90 top
L2602  180Ohm/100Mhz  [VX_L0603_H37_SMALL]  224.44 54.21 0 top
L2603  180Ohm/100Mhz  [VX_L0603_H37_SMALL]  230.74 62.39 0 top
L3300  4.7uH  [VX_INDUCTOR_2P_118X118_MAG]  284.08 95.15 90 top
L3301  600Ohm/100Mhz  [VX_L0603_H37_SMALL]  278.24 93.45 180 bottom
L3302  600Ohm/100Mhz  [VX_L0603_H37_SMALL]  280.52 90.53 0 top
L3400  90OHM/100MHz  [VX_2R4P_CHOKE1243_4P_CO_H40]  304.65 144.63 270 bottom
L3401  90OHM/100MHz  [VX_2R4P_CHOKE1243_4P_CO_H40]  304.65 147.05 270 bottom
L3402  90OHM/100MHz  [VX_2R4P_CHOKE1243_4P_CO_H40]  304.65 149.84 270 bottom
L3403  90OHM/100MHz  [VX_2R4P_CHOKE1243_4P_CO_H40]  304.65 153.02 270 bottom
L3600  600Ohm/100Mhz  [VX_L0603_H37_SMALL]  2.14 42.27 0 top
L3601  600Ohm/100Mhz  [VX_L0603_H37_SMALL]  2.14 19.54 180 top
L3606  600Ohm/100Mhz  [VX_L0603_H37_SMALL]  12.68 35.03 0 top
L3701  120Ohm/100Mhz  [VX_L0603_H37_SMALL]  229.6 18.78 90 top
L3702  120Ohm/100Mhz  [VX_L0603_H37_SMALL]  230.82 18.78 90 top
L3703  120Ohm/100Mhz  [VX_L0603_H37_SMALL]  233.11 18.81 90 top
L3704  120Ohm/100Mhz  [VX_L0603_H37_SMALL]  234.33 18.81 90 top
L4500  90OHM/100MHz  [VX_2R4P_CHOKE1243_4P_CO_H40]  104.88 182.1 0 bottom
L4501  90OHM/100MHz  [VX_2R4P_CHOKE1243_4P_CO_H40]  124.69 184.89 0 bottom
L4502  90OHM/100MHz  [VX_2R4P_CHOKE1243_4P_CO_H40]  121.39 184.89 0 bottom
L4503  90OHM/100MHz  [VX_2R4P_CHOKE1243_4P_CO_H40]  119.11 184.89 0 bottom
L4504  90OHM/100MHz  [VX_2R4P_CHOKE1243_4P_CO_H40]  116.82 184.89 0 bottom
L4505  90OHM/100MHz  [VX_2R4P_CHOKE1243_4P_CO_H40]  114.41 184.89 0 bottom
L4800  90ohm  [VX_CHOKE_4P_39X49_QUIE_H24]  307.19 94.64 270 top
L4801  90ohm  [VX_CHOKE_4P_39X49_QUIE_H24]  306.83 103.28 270 top
L4802  90ohm  [VX_CHOKE_4P_39X49_QUIE_H24]  306.84 106.07 270 top
L4803  90ohm  [VX_CHOKE_4P_39X49_QUIE_H24]  307.05 91.72 270 top
L5300  70Ohm/100Mhz  [VX_L0603_H37_SMALL]  292.87 100.64 180 top
L5301  90OHM/100MHz  [VX_2R4P_CHOKE1243_4P_CO_H40]  290.56 88.63 270 bottom
L5302  70Ohm/100Mhz  [VX_L0603_H37_SMALL]  292.87 102.01 180 top
L5500  90OHM/100MHz  [VX_2R4P_CHOKE1243_4P_CO_H40]  306.69 54.46 90 top
L5501  90OHM/100MHz  [VX_2R4P_CHOKE1243_4P_CO_H40]  308.21 50.27 180 bottom
L5502  90OHM/100MHz  [VX_2R4P_CHOKE1243_4P_CO_H40]  306.69 52.18 90 top
L5503  90OHM/100MHz  [VX_2R4P_CHOKE1243_4P_CO_H40]  303.76 78.98 90 top
L5504  90OHM/100MHz  [VX_2R4P_CHOKE1243_4P_CO_H40]  305.42 79.48 270 bottom
L5505  90OHM/100MHz  [VX_2R4P_CHOKE1243_4P_CO_H40]  303.76 76.56 90 top
L6001  33ohm  [VX_L0805_H43_SMALL]  3.49 68.54 90 top
L6002  33ohm  [VX_L0805_H43_SMALL]  5.36 68.54 90 top
L6003  33ohm  [VX_L0805_H43_SMALL]  7.19 68.54 90 top
L6700  70Ohm/100Mhz  [VX_L0603_H37_SMALL]  11.03 45.07 0 top
L6701  70Ohm/100Mhz  [VX_L0603_H37_SMALL]  11.03 43.8 0 top
L7100  30Ohm/100Mhz  [VX_L0603_SMALL]  149.21 60.43 180 top
L7201  30Ohm/100Mhz 0603  [VX_L0603_H37_SMALL]  135.06 82.76 0 top
L7202  30Ohm/100Mhz 0603  [VX_L0603_H37_SMALL]  135.06 84.13 0 top
L7205  300Ohm/100Mhz  [VX_L0603_H37_SMALL]  135.06 79.48 0 top
L7401  180Ohm/100Mhz  [VX_L0603_H37_SMALL]  135.36 53.45 90 bottom
L7402  180Ohm/100Mhz  [VX_L0603_H37_SMALL]  135.36 58.15 270 bottom
L7403  180Ohm/100Mhz  [VX_L0603_H37_SMALL]  149.05 64.5 90 bottom
L7404  180Ohm/100Mhz  [VX_L0603_H37_SMALL]  152.94 64.07 180 bottom
L8000  0.12uH  [VX_INDUCTOR_2P_274X260]  80.88 155.56 0 bottom
L8001  0.12uH  [VX_INDUCTOR_2P_274X260]  80.88 171.05 0 bottom
L8002  0.12uH  [VX_INDUCTOR_2P_274X260]  80.88 163.3 0 bottom
L8003  0.12uH  [VX_INDUCTOR_2P_274X260]  52.56 160.38 0 top
L8004  0.12uH  [VX_INDUCTOR_2P_274X260]  62.72 160.38 180 top
L8005  0.36uH  [VX_INDUCTOR_2P_274X260]  94.6 150.48 0 top
L8100  3.3uH  [VX_CHOKE_2P_543X496]  270.49 77.45 180 bottom
L8101  3.3uH  [VX_CHOKE_2P_543X496]  262.08 20.17 180 bottom
L8200  0.68UH  [VX_INDUCTOR_2P_274X260]  213.21 15.09 180 top
L8300  0.36uH  [VX_INDUCTOR_2P_274X260]  27.79 79.48 90 top
L8601  1UH  [VX_INDUCTOR_2P_268X268_MIC]  120.92 67.29 270 top
L8701  0.22uH  [VX_INDUCTOR_2P_439X394_M157]  179.43 164.83 270 bottom
L8702  0.22uH  [VX_INDUCTOR_2P_439X394_M157]  140.21 164.83 270 bottom
L8703  0.22uH  [VX_INDUCTOR_2P_439X394_M157]  154.64 164.83 270 bottom
L8704  0.22uH  [VX_INDUCTOR_2P_439X394_M157]  167.62 164.83 270 bottom
L8800  3.3UH  [VX_INDUCTOR_2P_291X264]  292.59 23.19 0 top
L8900  0.36UH  [VX_CHOKE_2P_453X394]  221.98 88.63 90 bottom
L8901  0.36UH  [VX_CHOKE_2P_453X394]  233.41 88.25 90 bottom
L9400  0.68UH  [VX_INDUCTOR_2P_274X260]  112.25 166.22 270 bottom
L9500  1UH  [VX_INDUCTOR_2P_268X268_MIC]  99.96 8.95 180 top
L9600  1UH  [VX_INDUCTOR_2P_268X268_MIC]  120.47 140.82 90 bottom
L9701  0.22uH  [VX_INDUCTOR_2P_439X394_M157]  204.07 160.05 270 bottom
L9702  0.22uH  [VX_INDUCTOR_2P_439X394_M157]  192.51 160.05 270 bottom
LC800  0.1UF/6.3V  [VX_C0402_SMALL]  242.58 191.59 270 top
LC801  0.1UF/6.3V  [VX_C0402_SMALL]  242.47 189.55 90 top
LC802  0.1UF/6.3V  [VX_C0402_SMALL]  231.04 187.34 90 top
LC803  0.1UF/6.3V  [VX_C0402_SMALL]  226.95 191.96 180 top
LLED800  RED  [VX_LED_2P_39X20_EVERLIG]  243.7 189.45 270 bottom
LLED801  RED  [VX_LED_2P_39X20_EVERLIG]  236.19 189.46 270 bottom
LLED802  RED  [VX_LED_2P_39X20_EVERLIG]  229.7 189.45 270 bottom
LLED803  YELLOW  [VX_LED_2P_39X20_EVERLIG]  237.2 189.45 270 bottom
LQ800  2N7002K-T1-GE3  [VX_SOT23_H44]  245.15 191.07 180 top
LQ801  2N7002K-T1-GE3  [VX_SOT23_H44]  245.09 187.84 180 top
LQ802  2N7002K-T1-GE3  [VX_SOT23_H44]  228.32 187.85 0 top
LQ803  UM6K1NG1DTN  [VX_SC70_S6]  229.79 190.85 90 top
LR800  1.2KOhm  [VX_R0603_H22_SMALL]  240.01 191.58 180 top
LR801  220Ohm  [VX_R0603_H28_SMALL]  242.29 187.64 90 top
LR802  1.2KOhm  [VX_R0603_H22_SMALL]  223.7 186.88 180 top
LR803  1.2KOhm  [VX_R0603_H22_SMALL]  249.46 187.21 0 top
LR804  10KOhm  [VX_R0402_SMALL]  226.95 190.95 0 top
NOREF  -  []  227.17 175 0 top
NOREF#2  -  [unnamed#2]  5.08 200.62 0 top
NOREF#3  -  []  130.34 23.08 0 top
NOREF#4  -  [unnamed#2]  319.42 -6.92 0 top
NOREF#5  -  [unnamed#3]  292.75 200.62 0 top
NOREF#6  -  [unnamed#3]  310.53 -6.92 0 top
NOREF#7  -  [unnamed#3]  13.97 -6.92 0 top
NOREF#8  -  [unnamed#3]  86.05 -6.92 0 top
NOREF#9  -  [unnamed#2]  5.08 -6.92 0 top
NOREF#10  -  [unnamed#2]  319.42 200.62 0 top
NOREF#11  -  [unnamed#3]  68.81 2.65 0 top
NOREF#12  -  [unnamed#3]  31.75 200.62 0 top
NOREF#13  -  [unnamed#3]  287.88 152.21 0 top
NOREF#14  -  []  266.43 -5.65 0 top
NOREF#15  -  []  228.69 188.85 0 top
NOREF#16  -  [unnamed#3]  238.45 200.62 0 top
NOREF#17  -  []  156.47 4.9 0 top
NOREF#18  -  []  66.53 199.35 0 top
NOREF#19  -  [unnamed#3]  41.64 191.12 0 top
NOREF#20  -  []  135.14 200.62 0 top
NOREF#21  -  []  86.98 -40.49 0 top
NOREF#22  -  [unnamed#3]  86.05 200.62 180 bottom
NOREF#23  -  [unnamed#3]  287.67 200.62 180 bottom
NOREF#24  -  [unnamed#3]  282.4 32.87 180 bottom
NOREF#25  -  []  135.11 200.64 180 bottom
NOREF#26  -  [unnamed#3]  19.05 -6.92 180 bottom
NOREF#27  -  []  249.78 186.67 180 bottom
NOREF#28  -  [unnamed#3]  305.45 -6.92 180 bottom
NOREF#29  -  []  246.54 191.5 180 bottom
NOREF#30  -  []  72.5 -5.65 180 bottom
NOREF#31  -  []  256.9 199.35 180 bottom
NOREF#32  -  [unnamed#3]  41.64 191.12 180 bottom
NOREF#33  -  [unnamed#3]  238.45 -6.92 180 bottom
NOREF#34  -  [unnamed#3]  69.83 2.65 180 bottom
NOREF#35  -  [unnamed#3]  36.83 200.62 180 bottom
Q0702  2N7002  [VX_SOT23_H43]  66.53 128.89 90 bottom
Q1201  2N7002  [VX_SOT23_H43]  287.38 67.29 90 top
Q1202  2N7002  [VX_SOT23_H43]  290.61 67.32 90 top
Q2301  2N7002  [VX_SOT23_H43]  223.12 36.53 90 bottom
Q2601  SI2301CDS-T1-GE3  [VX_SOT23_2D4_H44]  248.39 44.65 270 top
Q2602  BC856BS  [VX_SOT363_PHILIPS]  249.79 48.39 0 top
Q2801  2N7002  [VX_SOT23_H43]  249.79 64.24 180 top
Q3101  UM6K1NG1DTN  [VX_SC70_S6]  209.15 37.95 270 top
Q3102  UM6K1NG1DTN  [VX_SC70_S6]  47.35 125.97 270 top
Q3107  IRFML8244TRPBF  [VX_SOT23_2D4_H44]  212.32 25 180 top
Q3601  UM6K1NG1DTN  [VX_SC70_S6]  21.7 20.81 180 top
Q3602  2N7002  [VX_SOT23_H43]  20.81 24.49 0 top
Q4501  IRFML8244TRPBF  [VX_SOT23_2D4_H44]  101.96 181.46 0 bottom
Q4601  UM6K1NG1DTN  [VX_SC70_S6]  289.79 119.23 90 top
Q5001  PMBS3904  [VX_SOT23_H43]  257.03 88.29 0 top
Q5002  UM6K1NG1DTN  [VX_SC70_S6]  130.16 28.68 270 top
Q5300  PMV33UPE  [VX_SOT23_2D4_T01_H43]  296.32 99.57 90 top
Q5301  2N7002  [VX_SOT23_H43]  295.31 95.59 270 top
Q5302  2N7002  [VX_SOT23_H43]  292.11 95.59 270 top
Q5303  2N7002  [VX_SOT23_H43]  282.3 89.77 270 bottom
Q5304  2N7002  [VX_SOT23_H43]  279 89.77 270 bottom
Q5701  2N7002  [VX_SOT23_H43]  205.59 138.74 0 top
Q5702  2N7002  [VX_SOT23_H43]  122.79 134.47 0 top
Q5703  2N7002  [VX_SOT23_H43]  231.37 28.43 0 bottom
Q5704  2N7002  [VX_SOT23_H43]  200.01 51.42 0 bottom
Q5705  2N7002  [VX_SOT23_H43]  123.09 142.12 90 top
Q5706  2N7002  [VX_SOT23_H43]  139.81 34.53 90 bottom
Q5707  2N7002  [VX_SOT23_H43]  138.37 29.78 0 bottom
Q5708  2N7002  [VX_SOT23_H43]  20.81 62.85 0 top
Q5709  2N7002  [VX_SOT23_H43]  19.54 59.04 90 top
Q5710  2N7002  [VX_SOT23_H43]  120.5 8.74 90 top
Q5711  2N7002  [VX_SOT23_H43]  273.31 97.09 180 bottom
Q5712  2N7002  [VX_SOT23_H43]  276.69 69.1 180 bottom
Q5713  2N7002  [VX_SOT23_H43]  282.2 66.78 270 bottom
Q5714  2N7002  [VX_SOT23_H43]  127.69 86.06 0 bottom
Q5715  2N7002  [VX_SOT23_H43]  132.57 170.77 180 bottom
Q6001  2N7002  [VX_SOT23_H43]  307.19 74.2 180 bottom
Q6701  2N7002  [VX_SOT23_H43]  12.88 41.26 180 top
Q7202  PMV33UPE  [VX_SOT23_2D4_T01_H43]  290.18 123.81 270 top
Q7203  PMV33UPE  [VX_SOT23_2D4_T01_H43]  290.18 127.49 270 top
Q7204  2N7002  [VX_SOT23_H43]  285.22 87.87 180 top
Q7205  2N7002  [VX_SOT23_H43]  285.22 81.9 180 top
Q7206  UM6K1NG1DTN  [VX_SC70_S6]  285.1 116.95 0 top
Q7401  2N7002  [VX_SOT23_H43]  132.29 77.83 0 bottom
Q7402  2N7002  [VX_SOT23_H43]  132.31 74.63 0 bottom
Q7405  2N7002  [VX_SOT23_H43]  141.2 65.51 180 top
Q7406  PMV33UPE  [VX_SOT23_2D4_T01_H43]  138.2 72.65 90 top
Q7407  2N7002  [VX_SOT23_H43]  187.74 167.85 90 top
Q7600  PJA138K_R1_00001  [VX_SOT23_2D4_H43]  156.6 137.95 0 bottom
Q7700  PJA138K_R1_00001  [VX_SOT23_2D4_H43]  204.45 128.13 270 bottom
Q7800  PJA138K_R1_00001  [VX_SOT23_2D4_H43]  205.82 90.86 270 bottom
Q7900  PJA138K_R1_00001  [VX_SOT23_2D4_H43]  171.35 47.23 180 bottom
Q8001  SISA10DN-T1-GE3  [VX_SI7501DN_H44]  92.34 156.09 270 top
Q8002  SISA14DN-T1-GE3  [VX_SI7501DN_H44]  96.22 160.69 0 top
Q8101  SISA10DN-T1-GE3  [VX_SI7501DN_H44]  263.25 68.43 180 bottom
Q8102  SISA14DN-T1-GE3  [VX_SI7501DN_H44]  268.84 68.43 0 bottom
Q8103  SISA10DN-T1-GE3  [VX_SI7501DN_H44]  272.01 17.63 270 bottom
Q8104  SISA14DN-T1-GE3  [VX_SI7501DN_H44]  272.52 23.22 90 bottom
Q8106  UM6K1NG1DTN  [VX_SC70_S6]  260.46 66.4 90 top
Q8300  SIRA14DP-T1-GE3  [VX_SI7850DP]  23.96 71.74 90 top
Q8301  SIRA10DP-T1-GE3  [VX_SI7850DP]  31.35 69.86 0 top
Q8701  SIRA02DP-T1-GE3  [VX_SI7850DP]  183.11 176.61 0 bottom
Q8702  SIRA14DP-T1-GE3  [VX_SI7850DP]  173.97 182.38 0 top
Q8703  SIRA02DP-T1-GE3  [VX_SI7850DP]  143.74 176.61 0 bottom
Q8704  SIRA14DP-T1-GE3  [VX_SI7850DP]  136 175.9 0 top
Q8705  SIRA02DP-T1-GE3  [VX_SI7850DP]  152.25 176.61 0 bottom
Q8706  SIRA14DP-T1-GE3  [VX_SI7850DP]  150.09 184.92 0 top
Q8707  SIRA02DP-T1-GE3  [VX_SI7850DP]  165.39 176.61 0 bottom
Q8708  SIRA14DP-T1-GE3  [VX_SI7850DP]  168 182.38 0 top
Q8709  SIRA14DP-T1-GE3  [VX_SI7850DP]  156.06 183.27 0 top
Q8710  SIRA14DP-T1-GE3  [VX_SI7850DP]  179.94 182.38 0 top
Q8711  SIRA14DP-T1-GE3  [VX_SI7850DP]  162.03 182.38 0 top
Q8712  SIRA14DP-T1-GE3  [VX_SI7850DP]  130.03 175.9 0 top
Q8713  SIRA02DP-T1-GE3  [VX_SI7850DP]  177.2 176.61 0 bottom
Q8714  SIRA02DP-T1-GE3  [VX_SI7850DP]  137.78 176.61 0 bottom
Q8715  SIRA02DP-T1-GE3  [VX_SI7850DP]  158.22 176.61 0 bottom
Q8716  SIRA02DP-T1-GE3  [VX_SI7850DP]  171.3 176.61 0 bottom
Q8800  SM4372NAKPC-TRG  [VX_DFN_5P_50_209X228]  294.27 16.82 90 top
Q8801  SM4372NAKPC-TRG  [VX_DFN_5P_50_209X228]  6.92 79 90 top
Q8802  SM4372NAKPC-TRG  [VX_DFN_5P_50_209X228]  16.94 81.46 0 top
Q8803  IRF8707PBF  [VX_SOIC_8P_50_197X236]  284.84 21.32 180 top
Q8804  IRF8707PBF  [VX_SOIC_8P_50_197X236]  277.48 21.32 0 top
Q8805  2N7002  [VX_SOT23_H43]  272.52 40.24 0 top
Q8806  2N7002  [VX_SOT23_H43]  269.22 31.48 90 top
Q8807  UM6K1NG1DTN  [VX_SC70_S6]  266.17 31.48 180 top
Q8810  2N7002  [VX_SOT23_H43]  241.66 16.77 270 bottom
Q8901  SIRA14DP-T1-GE3  [VX_SI7850DP]  226.96 92.18 270 top
Q8902  SIRA10DP-T1-GE3  [VX_SI7850DP]  243.44 87.36 270 bottom
Q8903  SIRA10DP-T1-GE3  [VX_SI7850DP]  221.34 97.92 90 bottom
Q8904  SIRA14DP-T1-GE3  [VX_SI7850DP]  237.72 88.81 90 top
Q9102  68@-5mA/Vceo=+/-50V  [VX_SOT353]  185.15 30.21 270 top
Q9103  68@-5mA/Vceo=+/-50V  [VX_SOT353]  179.05 22.56 270 top
Q9104  68@-5mA/Vceo=+/-50V  [VX_SOT353]  242.04 26.91 180 top
Q9105  IRFML8244TRPBF  [VX_SOT23_2D4_H44]  241.28 23.48 270 top
Q9106  68@-5mA/Vceo=+/-50V  [VX_SOT353]  131.73 72.5 0 top
Q9107  IRFML8244TRPBF  [VX_SOT23_2D4_H44]  131.24 77.68 90 top
Q9200  UM6K1NG1DTN  [VX_SC70_S6]  175.11 39.25 270 top
Q9701  SIRA14DP-T1-GE3  [VX_SI7850DP]  202.04 176.92 0 top
Q9702  SIRA10DP-T1-GE3  [VX_SI7850DP]  200.89 172.01 0 bottom
Q9703  SIRA10DP-T1-GE3  [VX_SI7850DP]  206.79 172.01 0 bottom
Q9704  SIRA14DP-T1-GE3  [VX_SI7850DP]  196.07 176.92 0 top
Q9705  SIRA10DP-T1-GE3  [VX_SI7850DP]  194.98 172.02 0 bottom
Q9706  SIRA10DP-T1-GE3  [VX_SI7850DP]  189.08 172.02 0 bottom
R0300  24.9Ohm  [VX_R0402_SMALL]  114.57 129.27 180 top
R0302  20Ohm  [VX_R0402_SMALL]  117.23 121.6 0 top
R0504  121OHM  [VX_R0402_SMALL]  120.63 101.07 180 bottom
R0505  2Ohm  [VX_R0603_H24_SMALL]  67.86 100.52 180 top
R0506  75Ohm  [VX_R0402_SMALL]  120.83 99.14 180 bottom
R0507  100Ohm  [VX_R0402_SMALL]  121.01 98.03 0 bottom
R0508  2Ohm  [VX_R0603_H24_SMALL]  63.46 103.97 180 top
R0510  24.9Ohm  [VX_R0402_SMALL]  67.8 103.11 90 top
R0511  24.9Ohm  [VX_R0402_SMALL]  65.13 102.34 90 top
R0600  24.9Ohm  [VX_R0402_SMALL]  120.63 100.18 180 bottom
R0700  1KOhm  [VX_R0402_SMALL]  68.56 118.98 90 top
R0701  1KOhm  [VX_R0402_SMALL]  73.4 123.76 180 top
R0702  1KOhm  [VX_R0402_SMALL]  76.85 121.95 0 top
R0703  1KOhm  [VX_R0402_SMALL]  73.87 118.3 180 top
R0704  10KOhm  [VX_R0402_SMALL]  67.71 102.9 0 bottom
R0705  1KOhm  [VX_R0402_SMALL]  65.8 120.17 180 bottom
R0706  1KOhm  [VX_R0402_SMALL]  68.54 127.58 90 bottom
R0707  100Ohm  [VX_R0402_SMALL]  70.57 125.03 0 top
R0708  56Ohm  [VX_R0402_SMALL]  70.57 125.86 180 top
R0709  1KOhm  [VX_R0402_SMALL]  74.4 119.54 90 top
R0717  220Ohm  [VX_R0402_SMALL]  74.56 125.31 90 top
R0723  1KOhm  [VX_R0402_SMALL]  74.86 120.76 0 top
R0724  1KOhm  [VX_R0402_SMALL]  72.18 118.29 0 top
R0725  1KOhm  [VX_R0402_SMALL]  71.08 122.03 0 top
R0727  499Ohm  [VX_R0402_SMALL]  70.01 127.99 0 bottom
R0728  1.2KOhm  [VX_R0402_SMALL]  66.97 107.91 180 bottom
R0729  1KOhm  [VX_R0402_SMALL]  124.18 101.1 180 bottom
R0730  60.4Ohm  [VX_R0402_SMALL]  124.18 100.21 180 bottom
R0731  20Ohm  [VX_R0402_SMALL]  70.02 129.65 0 bottom
R0733  33Ohm  [VX_R0402_SMALL]  159.39 28.12 180 bottom
R0734  0Ohm  [VX_R0402_0OHM_SMALL]  70.65 101.81 270 bottom
R0738  51Ohm  [VX_R0402_SMALL]  66.29 121.83 180 top
R0739  51Ohm  [VX_R0402_SMALL]  68.47 124.11 180 bottom
R0740  51Ohm  [VX_R0402_SMALL]  70.01 128.81 180 bottom
R0741  51Ohm  [VX_R0402_SMALL]  70.14 123.76 180 bottom
R0742  49.9Ohm  [VX_R0402_SMALL]  68.71 121.88 90 bottom
R0743  30OHM  [VX_R0402_SMALL]  110.01 121.19 270 top
R0744  1KOhm  [VX_R0402_SMALL]  67.04 120.4 90 bottom
R0745  1KOhm  [VX_R0402_SMALL]  73.87 117.05 0 top
R0746  12.1ohm  [VX_R0201_H10]  228 74.1 180 top
R0747  45.3Ohm  [VX_R0402_SMALL]  70.39 127.11 0 top
R0751  100KOhm  [VX_R0402_SMALL]  146.41 27.41 90 bottom
R0752  0Ohm  [VX_R0402_0OHM_SMALL]  117.23 122.51 180 top
R0753  0Ohm  [VX_R0402_0OHM_SMALL]  117.23 123.37 180 top
R0754  1KOhm  [VX_R0402_SMALL]  72.62 117.08 90 top
R0755  10KOhm  [VX_R0402_SMALL]  67.71 102.04 0 bottom
R0756  0Ohm  [VX_R0402_0OHM_SMALL]  117.89 78.16 180 bottom
R0900  0Ohm  [VX_R0603_0OHM_H28_SMALL]  96.03 122.18 270 top
R0901  0Ohm  [VX_R0603_0OHM_H28_SMALL]  94.81 122.18 270 top
R0902  0Ohm  [VX_R0603_0OHM_H28_SMALL]  63.48 185.02 90 top
R0903  0Ohm  [VX_R0603_0OHM_H28_SMALL]  64.75 185.02 90 top
R0904  0Ohm  [VX_R0603_0OHM_H28_SMALL]  72.78 141.71 0 top
R1000  0Ohm  [VX_R0603_0OHM_H28_SMALL]  80.79 117.38 180 top
R1002  0Ohm  [VX_R0603_0OHM_H28_SMALL]  78.38 122.08 270 top
R1003  0Ohm  [VX_R0603_0OHM_H28_SMALL]  80.79 114.84 180 top
R1004  100Ohm  [VX_R0402_SMALL]  78.45 120.17 90 top
R1005  0Ohm  [VX_R0402_0OHM_SMALL]  77.6 120.17 270 top
R1006  0Ohm  [VX_R0603_0OHM_H28_SMALL]  80.79 116.11 180 top
R1007  0Ohm  [VX_R0603_0OHM_H28_SMALL]  64.61 108.21 0 bottom
R1008  0Ohm  [VX_R0603_0OHM_H28_SMALL]  80.79 113.57 180 top
R1009  100Ohm  [VX_R0402_SMALL]  75.13 115.81 90 top
R1010  0Ohm  [VX_R0402_0OHM_SMALL]  74.67 114.54 0 top
R1011  0Ohm  [VX_R0603_0OHM_H28_SMALL]  75.35 111.82 0 top
R1012  0Ohm  [VX_R0603_0OHM_H28_SMALL]  74.58 127.54 90 top
R1013  100Ohm  [VX_R0402_SMALL]  86.89 110.9 0 top
R1014  49.9Ohm  [VX_R0402_SMALL]  71.39 123.77 0 top
R1015  49.9Ohm  [VX_R0402_SMALL]  67.88 121.88 90 bottom
R1016  49.9Ohm  [VX_R0402_SMALL]  70.14 122.87 180 bottom
R1101  3.01KOHM  [VX_R0402_SMALL]  293.55 36.43 270 bottom
R1102  14KOHM  [VX_R0402_SMALL]  282.94 51.29 180 bottom
R1103  3.3KOhm  [VX_R0402_SMALL]  275.55 62.21 90 top
R1104  3.3KOhm  [VX_R0402_SMALL]  276.97 51.04 180 top
R1105  3.3KOhm  [VX_R0402_SMALL]  273.67 57.13 90 top
R1106  3.3KOhm  [VX_R0402_SMALL]  276.43 62.21 90 top
R1107  4.75KOhm  [VX_R0402_SMALL]  295.74 43.11 0 bottom
R1108  14KOHM  [VX_R0402_SMALL]  287.88 37.33 90 bottom
R1109  0Ohm  [VX_R0402_0OHM_SMALL]  274.63 46.74 0 bottom
R1110  10KOhm  [VX_R0402_SMALL]  297.69 43.79 180 bottom
R1111  10KOhm  [VX_R0402_SMALL]  276.99 49.41 90 top
R1112  10KOhm  [VX_R0402_SMALL]  284.59 47.48 0 bottom
R1113  10KOhm  [VX_R0402_SMALL]  282.94 47.48 180 bottom
R1114  10KOhm  [VX_R0402_SMALL]  282.94 49.33 180 bottom
R1115  10KOhm  [VX_R0402_SMALL]  282.94 48.5 180 bottom
R1116  0Ohm  [VX_R0402_0OHM_SMALL]  277.88 59.36 90 bottom
R1117  0Ohm  [VX_R0402_0OHM_SMALL]  272.83 52.26 180 bottom
R1118  1MOhm  [VX_R0402_SMALL]  301.86 42.2 270 top
R1119  10KOhm  [VX_R0402_SMALL]  282.81 45.42 0 top
R1120  100KOhm  [VX_R0402_SMALL]  280.9 52.03 0 bottom
R1121  0Ohm  [VX_R0402_0OHM_SMALL]  282.94 52.18 0 bottom
R1122  1MOhm  [VX_R0402_SMALL]  303.79 42.07 270 top
R1123  499Ohm  [VX_R0402_SMALL]  296.4 34.53 180 bottom
R1124  499Ohm  [VX_R0402_SMALL]  298.39 36 90 bottom
R1125  100KOhm  [VX_R0402_SMALL]  294.52 47.99 90 top
R1126  100KOhm  [VX_R0402_SMALL]  303.64 43.29 0 top
R1127  100KOhm  [VX_R0402_SMALL]  300.97 42.2 270 top
R1128  100Ohm  [VX_R0402_SMALL]  282.94 52.69 180 top
R1129  100Ohm  [VX_R0402_SMALL]  283.04 46.74 180 top
R1130  10KOhm  [VX_R0402_SMALL]  296.14 50.02 180 top
R1131  10KOhm  [VX_R0402_SMALL]  282.94 53.58 180 top
R1132  10KOhm  [VX_R0402_SMALL]  282.94 50.91 180 top
R1133  100KOhm  [VX_R0402_SMALL]  283.32 56.62 0 bottom
R1134  10KOhm  [VX_R0402_SMALL]  297.72 42.95 180 bottom
R1135  10KOhm  [VX_R0402_SMALL]  282.94 51.8 180 top
R1136  0Ohm  [VX_R0402_0OHM_SMALL]  301.68 32.67 270 top
R1137  0Ohm  [VX_R0402_0OHM_SMALL]  300.41 33.21 0 top
R1138  10KOhm  [VX_R0402_SMALL]  289.54 49 90 bottom
R1139  100KOhm  [VX_R0402_SMALL]  290.24 49.12 90 top
R1140  2.2KOhm  [VX_R0402_SMALL]  292.97 49.13 90 top
R1141  2.2KOhm  [VX_R0402_SMALL]  291.7 49.13 90 top
R1142  100KOhm  [VX_R0402_SMALL]  289.54 46.08 270 bottom
R1143  2.2KOhm  [VX_R0402_SMALL]  287.64 43.16 180 bottom
R1144  2.2KOhm  [VX_R0402_SMALL]  281.12 50.41 270 bottom
R1145  10KOhm  [VX_R0402_SMALL]  284.63 54.08 270 bottom
R1146  10KOhm  [VX_R0402_SMALL]  284.97 49.41 180 top
R1154  100KOhm  [VX_R0402_SMALL]  285.11 39.68 90 bottom
R1155  100KOhm  [VX_R0402_SMALL]  285.11 38.06 270 bottom
R1159  0Ohm  [VX_R0603_0OHM_H28_SMALL]  306.93 43.61 90 top
R1160  0Ohm  [VX_R0603_0OHM_H28_SMALL]  300.92 41.26 90 bottom
R1161  10KOhm  [VX_R0402_SMALL]  284.97 48.55 0 top
R1164  0Ohm  [VX_R0603_0OHM_H28_SMALL]  300.46 43.54 90 bottom
R1165  100KOhm  [VX_R0402_SMALL]  296.53 47.99 90 top
R1166  100KOhm  [VX_R0402_SMALL]  288.19 48.17 90 top
R1167  100KOhm  [VX_R0402_SMALL]  287.31 48.17 90 top
R1168  100KOhm  [VX_R0402_SMALL]  287.64 44.05 0 bottom
R1169  100KOhm  [VX_R0402_SMALL]  287.28 42.27 0 bottom
R1170  100KOhm  [VX_R0402_SMALL]  287.64 46.84 0 bottom
R1171  100KOhm  [VX_R0402_SMALL]  287.64 44.94 0 bottom
R1172  100KOhm  [VX_R0402_SMALL]  287.64 45.96 0 bottom
R1201  100KOhm  [VX_R0402_SMALL]  288.93 73.03 0 top
R1203  100KOhm  [VX_R0402_SMALL]  288.93 72.17 180 top
R1205  100KOhm  [VX_R0402_SMALL]  292.69 76.84 0 top
R1206  100KOhm  [VX_R0402_SMALL]  292.69 75.93 180 top
R1207  80.6KOhm  [VX_R0402_SMALL]  297.08 73.77 0 top
R1208  22KOhm  [VX_R0402_SMALL]  297.08 74.66 0 top
R1209  0Ohm  [VX_R0402_0OHM_SMALL]  290.79 74.07 0 top
R1210  0Ohm  [VX_R0402_0OHM_SMALL]  290.71 73.03 0 top
R1212  0Ohm  [VX_R0402_0OHM_SMALL]  290.71 72.17 0 top
R1213  0Ohm  [VX_R0402_0OHM_SMALL]  300.54 70.97 270 top
R1214  0Ohm  [VX_R0402_0OHM_SMALL]  300.54 71.84 90 top
R1215  0Ohm  [VX_R0402_0OHM_SMALL]  298.71 70.97 270 top
R1216  0Ohm  [VX_R0402_0OHM_SMALL]  298.71 71.84 90 top
R1217  0Ohm  [VX_R0402_0OHM_SMALL]  300.54 70.11 270 top
R1218  15KOhm  [VX_R0402_SMALL]  291.45 52.69 0 top
R1221  0Ohm  [VX_R0402_0OHM_SMALL]  298.71 70.11 270 top
R1222  100KOhm  [VX_R0402_SMALL]  278.09 61.75 180 top
R1223  0Ohm  [VX_R0402_0OHM_SMALL]  278.09 63.48 0 top
R1224  10KOhm  [VX_R0402_SMALL]  289.13 56.9 0 top
R1225  10KOhm  [VX_R0402_SMALL]  289.13 56.04 0 top
R1226  100KOhm  [VX_R0402_SMALL]  289.16 53.7 0 top
R1227  10KOhm  [VX_R0402_SMALL]  286.46 55.49 180 top
R1228  10KOhm  [VX_R0402_SMALL]  284.93 56.95 270 top
R1229  10KOhm  [VX_R0402_SMALL]  295.38 62.59 90 top
R1230  10KOhm  [VX_R0402_SMALL]  285.78 56.95 270 top
R1231  3.3KOhm  [VX_R0402_SMALL]  287.47 56.95 270 top
R1232  3.3KOhm  [VX_R0402_SMALL]  286.64 56.95 270 top
R1233  100KOhm  [VX_R0402_SMALL]  300.97 52.31 0 top
R1234  100KOhm  [VX_R0402_SMALL]  300.97 53.32 0 top
R1235  100KOhm  [VX_R0402_SMALL]  299.02 53.78 0 top
R1236  100KOhm  [VX_R0402_SMALL]  301 54.21 0 top
R1238  0Ohm  [VX_R0402_0OHM_SMALL]  290.79 75.17 0 top
R1239  0Ohm  [VX_R0402_0OHM_SMALL]  278.09 62.62 0 top
R1240  0Ohm  [VX_R0402_0OHM_SMALL]  278.96 60.53 90 bottom
R1241  100KOhm  [VX_R0402_SMALL]  279.84 58.56 270 bottom
R1242  0Ohm  [VX_R0402_0OHM_SMALL]  292.64 68.69 270 top
R1243  0Ohm  [VX_R0402_0OHM_SMALL]  284.96 67.75 0 top
R1244  0Ohm  [VX_R0402_0OHM_SMALL]  276.08 61.78 180 bottom
R1245  300KOhm  [VX_R0402_SMALL]  297.31 72.32 180 top
R1246  100KOhm  [VX_R0402_SMALL]  296.7 71.1 270 top
R1247  0Ohm  [VX_R0402_0OHM_SMALL]  297.72 71.1 270 top
R1248  0Ohm  [VX_R0402_0OHM_SMALL]  291.14 70.42 90 top
R1301  0Ohm  [VX_R0603_0OHM_H28_SMALL]  285.48 85.71 0 bottom
R1302  0Ohm  [VX_R0402_0OHM_SMALL]  291.7 84.18 0 bottom
R1303  1KOhm  [VX_R0402_SMALL]  291.7 86.21 0 top
R1304  0Ohm  [VX_R0603_0OHM_H28_SMALL]  286.62 87.74 0 bottom
R1305  330Ohm  [VX_R0603_H28_SMALL]  277.67 89.14 90 top
R1306  0Ohm  [VX_R0402_0OHM_SMALL]  291.7 89.26 180 top
R1307  0Ohm  [VX_R0402_0OHM_SMALL]  291.7 90.28 180 top
R1308  0Ohm  [VX_R0402_0OHM_SMALL]  299.83 87.87 90 top
R1309  0Ohm  [VX_R0402_0OHM_SMALL]  297.92 87.87 90 top
